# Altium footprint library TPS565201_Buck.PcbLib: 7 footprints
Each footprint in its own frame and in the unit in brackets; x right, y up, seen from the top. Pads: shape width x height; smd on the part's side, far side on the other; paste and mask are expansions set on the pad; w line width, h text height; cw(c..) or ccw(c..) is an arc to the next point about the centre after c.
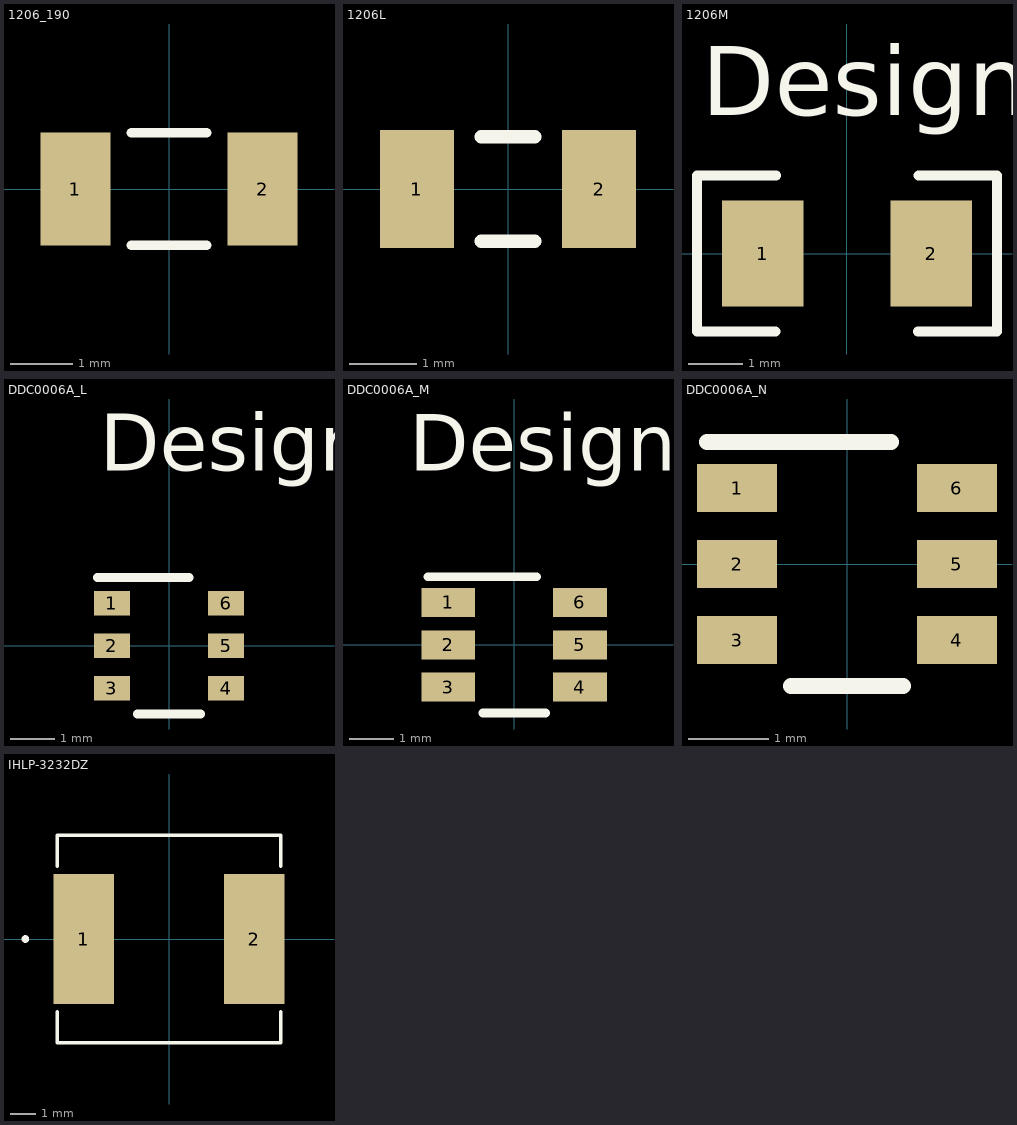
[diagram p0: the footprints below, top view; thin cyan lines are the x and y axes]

## 1206_190 [mil]
pads (2):
  rect 44x71 smd: 1(-59,0) 2(59,0)
Top Overlay:
  lines w6: -23.9,-35.5 23.9,-35.5 ; -23.9,35.5 23.9,35.5

## 1206L [mm]
pads (2):
  rect 1.1x1.75 smd paste+0 mask+0.051: 1(-1.35,0) 2(1.35,0)
Top Overlay:
  lines w0.2: -0.4,-0.775 0.4,-0.775 ; -0.4,0.775 0.4,0.775

## 1206M [mm]
pads (2):
  rect 1.5x1.95 smd paste+0 mask+0.051: 1(-1.55,0) 2(1.55,0)
Top Overlay:
  lines w0.178: -2.758,-1.43 -2.753,-1.435 ; -1.313,-1.435 -2.758,-1.435 -2.758,1.435 -1.303,1.435 ; 1.306,-1.435 2.761,-1.435 2.761,1.435 1.316,1.435 ; 2.756,1.435 2.761,1.43
  text "Designator9" at -2.667,2.54 h1.27

## DDC0006A_L [mm]
pads (6):
  rect 0.8x0.55 smd paste+0 mask+0.051: 1(-1.275,0.95) 2(-1.275,0) 3(-1.275,-0.95) 4(1.275,-0.95) 5(1.275,0) 6(1.275,0.95)
Top Overlay:
  lines w0.2: -1.603,1.525 0.45,1.525 ; -0.7,-1.524 0.7,-1.524
  text "Designator283" at -1.549,3.912 h1.27

## DDC0006A_M [mm]
pads (6):
  rect 1.2x0.65 smd paste+0 mask+0.051: 1(-1.475,0.95) 2(-1.475,0) 3(-1.475,-0.95) 4(1.475,-0.95) 5(1.475,0) 6(1.475,0.95)
Top Overlay:
  lines w0.2: -1.925,1.525 0.5,1.525 ; -0.7,-1.524 0.7,-1.524
  text "Designator284" at -2.35,3.9 h1.27

## DDC0006A_N [mm]
pads (6):
  rect 1x0.6 smd paste+0 mask+0.051: 1(-1.375,0.95) 2(-1.375,0) 3(-1.375,-0.95) 4(1.375,-0.95) 5(1.375,0) 6(1.375,0.95)
Top Overlay:
  lines w0.2: -1.75,1.525 0.55,1.525 ; -0.7,-1.524 0.7,-1.524

## IHLP-3232DZ [mil]
pads (2):
  rect 95x203 smd: 1(-133.5,0) 2(133.5,0)
Top Overlay:
  circle w6: c-225,0 r3
  lines w6: -175,-114.6 -175,-162.5 175,-162.5 175,-114.6 ; -175,114.6 -175,162.5 175,162.5 175,114.6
